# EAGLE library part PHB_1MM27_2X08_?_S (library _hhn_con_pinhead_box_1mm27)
Pin Header Box-Type, 1.27mm/0.5"/50mil Pitch, 2x08 Circuits, single gates in schematic Note: see library description for an important note about THT-version
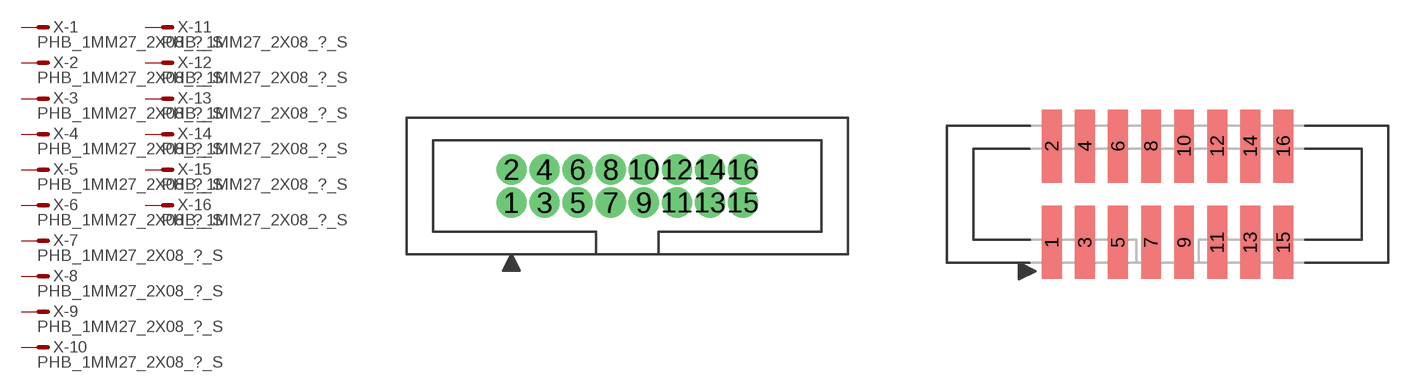
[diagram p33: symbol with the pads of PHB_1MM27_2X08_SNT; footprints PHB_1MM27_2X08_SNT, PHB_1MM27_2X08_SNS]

Designator prefix X; gates -1=M -2=M -3=M -4=M -5=M -6=M -7=M -8=M -9=M -10=M -11=M -12=M -13=M -14=M -15=M -16=M

## PHB_1MM27_2X08_SNT_S  [PHB_1MM27_2X08_SNT]
1  -1:S  pas
2  -2:S  pas
3  -3:S  pas
4  -4:S  pas
5  -5:S  pas
6  -6:S  pas
7  -7:S  pas
8  -8:S  pas
9  -9:S  pas
10  -10:S  pas
11  -11:S  pas
12  -12:S  pas
13  -13:S  pas
14  -14:S  pas
15  -15:S  pas
16  -16:S  pas

## PHB_1MM27_2X08_SNS_S  [PHB_1MM27_2X08_SNS]
Pads as for PHB_1MM27_2X08_SNT

## Footprint PHB_1MM27_2X08_SNT (pad centres in mm)
Pin Header Box-Type, 1.27mm Pitch, 2x08 circuits, Straight, No Locking, THT Important Note: Diameter in this lbr is set to a specific value (NOT 'auto' = 0), this is ignored by actual eagle versions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
drill 0.65 pad 1 round: 1 -4.445,-0.635; 2 -4.445,0.635; 3 -3.175,-0.635; 4 -3.175,0.635; 5 -1.905,-0.635; 6 -1.905,0.635; 7 -0.635,-0.635; 8 -0.635,0.635; 9 0.635,-0.635; 10 0.635,0.635; 11 1.905,-0.635; 12 1.905,0.635; 13 3.175,-0.635; 14 3.175,0.635; 15 4.445,-0.635; 16 4.445,0.635

## Footprint PHB_1MM27_2X08_SNS (pad centres in mm)
Pin Header Box-Type, 1.27mm Pitch, 2x08 circuits, Straight, No Locking, SMT
smd 0.76 x 2.8: 1 -4.445,-1.85; 2 -4.445,1.85; 3 -3.175,-1.85; 4 -3.175,1.85; 5 -1.905,-1.85; 6 -1.905,1.85; 7 -0.635,-1.85; 8 -0.635,1.85; 9 0.635,-1.85; 10 0.635,1.85; 11 1.905,-1.85; 12 1.905,1.85; 13 3.175,-1.85; 14 3.175,1.85; 15 4.445,-1.85; 16 4.445,1.85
